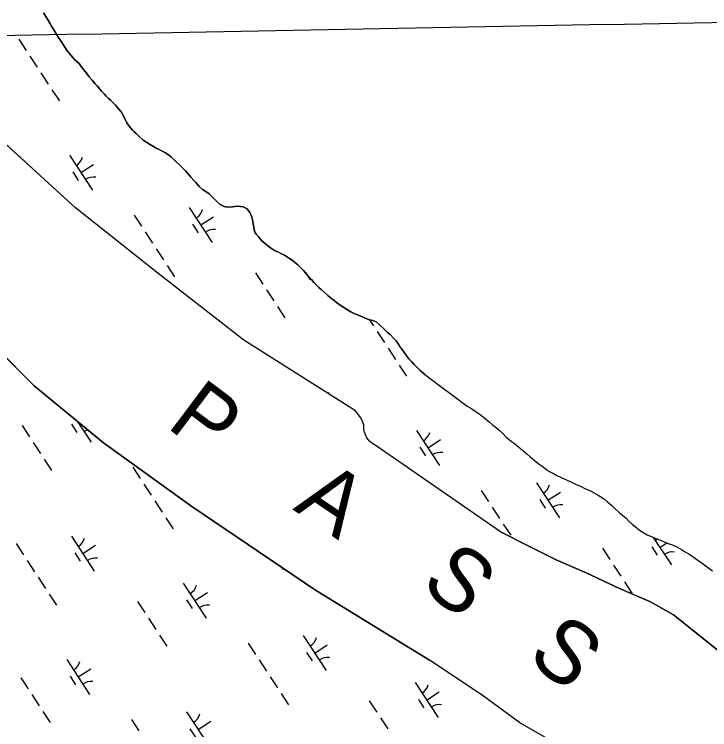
# Model space of a CAD drawing. Extents: x 3945642 to 3966284, y 206476 to 228921.
# Drawn here: x 3957964 to 3958793, y 217580 to 218434 of the extents above; entities that cross this region are included whole.
import ezdxf

# ---------------------------------------------------------------- set-up
doc = ezdxf.new("R2010")
doc.units = 0
for name, color, linetype in [('V-GRID-MAJR', 7, 'Continuous'), ('V-RIVR-IDEN', 7, 'Continuous'), ('V-TOPO-SHOR', 7, 'Continuous'), ('V-WETL-SWMP', 7, 'Continuous')]:
    doc.layers.add(name, color=color, linetype=linetype)

msp = doc.modelspace()

# ---------------------------------------------------------------- linework, layer by layer
at = {"layer": 'V-GRID-MAJR'}
msp.add_spline([(3951300.5, 218285.91), (3951621.83, 218291.8), (3956944.95, 218389.75), (3962268.05, 218488.48), (3962294.36, 218488.97)], degree=3, dxfattribs=at)
at = {"layer": 'V-TOPO-SHOR'}
for points in [[(3958094.57, 218310.93), (3958091.2, 218317.03), (3958086.44, 218322.83), (3958084.33, 218325.19), (3958080.83, 218328.73), (3958078.39, 218330.99), (3958076.06, 218333.25), (3958072.78, 218336.47), (3958070.55, 218338.62), (3958067.59, 218341.95), (3958065.58, 218344.31), (3958062.51, 218348.07), (3958060.08, 218350.75), (3958056.37, 218355.04), (3958052.46, 218359.55), (3958050.13, 218362.88), (3958046.33, 218367.49), (3958043.47, 218371.35), (3958040.83, 218374.78), (3958036.06, 218378.87), (3958033.31, 218381.98), (3958030.77, 218384.67), (3958026.96, 218389.71), (3958024.75, 218393.35), (3958021.05, 218398.71), (3958018.62, 218402.25), (3958015.14, 218407.51), (3958012.93, 218410.93), (3958011.03, 218414.36), (3958008.08, 218419.61), (3958006.08, 218422.93), (3958003.23, 218427.86), (3958001.33, 218430.96), (3957998.48, 218435.57)], [(3958543.75, 217815.94), (3958395.45, 217918.66), (3958390.25, 217921.68), (3958387.38, 217924.05), (3958384.32, 217927.91), (3958382.01, 217932.84), (3958381.06, 217935.62), (3958380.66, 217938.71), (3958380.48, 217942.98), (3958379.44, 217946.62), (3958377.02, 217951.86), (3958370.79, 217960.23), (3958237.29, 218044.6), (3958136.61, 218123.19), (3958036.58, 218202.74), (3957916.91, 218311.66)], [(3958453.5, 218003.59), (3958450.1, 218006.39), (3958447.45, 218008.75), (3958443.75, 218012.4), (3958440.15, 218016.06), (3958437.39, 218018.96), (3958434.43, 218022.29), (3958431.79, 218025.61), (3958428.19, 218030.54), (3958423.65, 218037.19), (3958421.97, 218039.98), (3958419.01, 218043.94), (3958416.47, 218046.52), (3958411.91, 218051.25), (3958408.52, 218054.26), (3958404.7, 218057.7), (3958398.87, 218063.18), (3958395.16, 218066.41), (3958391.33, 218067.93), (3958387.18, 218069.03), (3958384.2, 218070.11), (3958378.89, 218072.39), (3958371.86, 218075.22), (3958368.99, 218076.3), (3958364.95, 218078.36), (3958361.13, 218080.73), (3958355.39, 218084.61), (3958352.42, 218086.45), (3958347.86, 218089.79), (3958344.99, 218092.05), (3958340.54, 218095.6), (3958337.78, 218097.86), (3958333.54, 218101.41), (3958329.62, 218105.07), (3958326.86, 218107.54), (3958323.05, 218111.3), (3958320.93, 218113.66), (3958318.07, 218117.1), (3958313.52, 218122.25), (3958310.56, 218125.58), (3958308.55, 218127.83), (3958304.21, 218132.24), (3958301.77, 218134.39), (3958297.85, 218137.83), (3958295.19, 218139.99), (3958290.73, 218143), (3958285.74, 218145.92), (3958282.45, 218147.65), (3958277.88, 218150.03), (3958274.79, 218151.33), (3958270.65, 218153.6), (3958265.87, 218157.05), (3958261, 218161.46), (3958258.66, 218163.61), (3958255.17, 218167.47), (3958252, 218171.12), (3958250.21, 218174.55), (3958249.49, 218179.46), (3958248.67, 218183.2), (3958247.85, 218188.65), (3958246.18, 218193.67), (3958244.71, 218196.88), (3958241.22, 218201.28), (3958236.55, 218203.66), (3958230.26, 218204.45), (3958223.43, 218203.76), (3958217.77, 218203.48), (3958213.93, 218204.14), (3958208.3, 218206.96), (3958202.9, 218212.44), (3958200.46, 218215.12), (3958195.9, 218219.21), (3958193.15, 218221.25), (3958188.05, 218224.38), (3958184.55, 218227.5), (3958180, 218232.65), (3958177.77, 218235.23), (3958174.18, 218239.1), (3958170.79, 218243.28), (3958168.04, 218246.18), (3958164.02, 218250.48), (3958160.95, 218253.49), (3958156.39, 218258), (3958150.88, 218263.48), (3958146.42, 218266.6), (3958143.77, 218268.22), (3958139.94, 218270.38), (3958137.07, 218271.79), (3958132.71, 218273.96), (3958129.42, 218275.79), (3958124.64, 218278.49), (3958121.56, 218280.44), (3958117.42, 218283.24), (3958112.01, 218288.08), (3958108.83, 218291.2), (3958106.61, 218293.34), (3958104.49, 218295.49), (3958100.47, 218300.22), (3958097.94, 218304.07), (3958095.94, 218308.04), (3958094.57, 218310.93)], [(3957697, 218274.92), (3957707.71, 218265.35), (3957741.57, 218242.07), (3957792.74, 218191.99), (3957847.35, 218130.16), (3957917.47, 218059.68), (3957987.17, 217990.27), (3958070, 217922.04), (3958175.5, 217845.87), (3958322.86, 217746.14), (3958459.02, 217662.71)], [(3958453.5, 218003.59), (3958503.86, 217966.01), (3958509.32, 217962.82), (3958513.55, 217960.06), (3958516.55, 217957.99), (3958521.32, 217954.4), (3958525, 217951.5), (3958530.32, 217947.09), (3958533.86, 217944.05), (3958538.9, 217939.78), (3958541.9, 217937.02), (3958546.26, 217933.02), (3958550.48, 217928.89), (3958553.48, 217926.41), (3958556.75, 217923.79), (3958560.16, 217921.16), (3958565.47, 217916.75), (3958569.43, 217913.71), (3958575.01, 217909.02), (3958578.69, 217905.85), (3958584.42, 217901.16), (3958589.73, 217896.75), (3958593.41, 217894.12), (3958598.73, 217890.12), (3958602.28, 217887.91), (3958607.6, 217884.86), (3958610.74, 217883.2), (3958615.93, 217880.57), (3958619.48, 217879.18), (3958623.31, 217877.51), (3958629.04, 217874.74), (3958633.27, 217872.66), (3958639.83, 217869.75), (3958644.34, 217867.66), (3958650.89, 217864.75), (3958654.72, 217862.67), (3958660.31, 217859.63), (3958663.45, 217857.69), (3958667.81, 217854.65), (3958671.5, 217851.75), (3958676.4, 217847.34), (3958679.8, 217844.04), (3958685.52, 217838.66), (3958689.61, 217835.35), (3958693.43, 217832.04), (3958697.1, 217828.18), (3958701.19, 217824.6), (3958704.73, 217821.7), (3958710.6, 217817.15), (3958714.55, 217814.52), (3958718.65, 217812.31), (3958725.48, 217809.39), (3958730.12, 217807.45), (3958737.5, 217804.53), (3958742.42, 217802.44), (3958749.66, 217799.8), (3958753.89, 217797.72)], [(3958543.75, 217815.94), (3958577.61, 217798.82), (3958609.96, 217782.4), (3958645.93, 217766.86), (3958685.78, 217748.29), (3958722.65, 217732.15), (3958750.2, 217716.66), (3958774.13, 217697.59), (3958803.44, 217674.28)], [(3958753.89, 217797.72), (3958759.63, 217794.67), (3958763.31, 217792.46), (3958768.77, 217789.14), (3958774.36, 217785.41), (3958778.04, 217782.65), (3958782, 217780.02), (3958785.95, 217777.12), (3958792.36, 217772.43), (3958796.73, 217769.25)], [(3959513.7, 217029.24), (3959428.04, 217072.36), (3959348.4, 217116.4), (3959292.43, 217144.73), (3959207.19, 217188.95), (3959155.07, 217220.12), (3959090.4, 217255.2), (3959023.7, 217294.93), (3958962.33, 217334.09), (3958901.76, 217369.41), (3958818.07, 217421.27), (3958770.45, 217452.55), (3958717.55, 217491.38), (3958661.35, 217526.82), (3958607.62, 217564.15), (3958566.65, 217587.89), (3958521.77, 217620.93), (3958459.02, 217662.71)]]:
    msp.add_lwpolyline(points, dxfattribs=at)
at = {"layer": 'V-WETL-SWMP'}
for p, q in [((3957998.48, 218435.57), (3958001.33, 218430.96)), ((3958001.33, 218430.96), (3958003.23, 218427.86)), ((3958003.23, 218427.86), (3958006.08, 218422.93)), ((3958006.08, 218422.93), (3958008.08, 218419.61)), ((3958008.08, 218419.61), (3958011.03, 218414.36)), ((3958011.03, 218414.36), (3958012.93, 218410.93)), ((3958012.93, 218410.93), (3958015.14, 218407.5)), ((3958015.14, 218407.5), (3958018.62, 218402.25)), ((3957969.03, 218403.84), (3957977.8, 218390.45)), ((3958018.62, 218402.25), (3958021.05, 218398.71)), ((3958021.05, 218398.71), (3958024.75, 218393.35)), ((3958024.75, 218393.35), (3958026.96, 218389.71)), ((3958026.96, 218389.71), (3958030.77, 218384.67)), ((3957982.18, 218383.76), (3957990.95, 218370.38)), ((3958030.77, 218384.67), (3958033.31, 218381.98)), ((3958033.31, 218381.98), (3958036.06, 218378.87)), ((3958036.06, 218378.87), (3958040.83, 218374.78)), ((3958040.83, 218374.78), (3958043.47, 218371.35)), ((3958043.47, 218371.35), (3958046.33, 218367.49)), ((3958046.33, 218367.49), (3958050.13, 218362.88)), ((3957995.33, 218363.68), (3958004.1, 218350.3)), ((3958050.13, 218362.88), (3958052.46, 218359.55)), ((3958052.46, 218359.55), (3958056.37, 218355.04)), ((3958056.37, 218355.04), (3958060.08, 218350.75)), ((3958060.08, 218350.75), (3958062.51, 218348.07)), ((3958062.51, 218348.07), (3958065.58, 218344.31)), ((3958008.49, 218343.61), (3958017.25, 218330.23)), ((3958065.58, 218344.31), (3958067.59, 218341.95)), ((3958067.59, 218341.95), (3958070.55, 218338.62)), ((3958070.55, 218338.62), (3958072.78, 218336.47)), ((3958072.78, 218336.47), (3958076.06, 218333.25)), ((3958076.06, 218333.25), (3958078.39, 218330.99)), ((3958078.39, 218330.99), (3958080.83, 218328.73)), ((3958080.83, 218328.73), (3958084.32, 218325.19)), ((3958084.32, 218325.19), (3958086.44, 218322.83)), ((3958086.44, 218322.83), (3958091.2, 218317.03)), ((3958091.2, 218317.03), (3958094.57, 218310.93)), ((3958036.58, 218202.74), (3957916.91, 218311.66)), ((3958094.57, 218310.93), (3958095.94, 218308.04)), ((3958095.94, 218308.04), (3958097.94, 218304.07)), ((3958097.94, 218304.07), (3958100.47, 218300.22)), ((3958100.47, 218300.22), (3958104.49, 218295.49)), ((3958104.49, 218295.49), (3958106.61, 218293.34)), ((3958106.61, 218293.34), (3958108.83, 218291.2)), ((3958108.83, 218291.2), (3958112.01, 218288.08)), ((3958112.01, 218288.08), (3958117.42, 218283.24)), ((3958117.42, 218283.24), (3958121.56, 218280.44)), ((3958121.56, 218280.44), (3958124.64, 218278.49)), ((3958124.64, 218278.49), (3958129.42, 218275.79)), ((3958129.42, 218275.79), (3958132.71, 218273.96)), ((3958132.71, 218273.96), (3958137.07, 218271.79)), ((3958137.07, 218271.79), (3958139.94, 218270.38)), ((3958139.94, 218270.38), (3958143.77, 218268.22)), ((3958029.27, 218265.58), (3958056.67, 218223.76)), ((3958143.77, 218268.22), (3958146.42, 218266.6)), ((3958146.42, 218266.6), (3958150.88, 218263.48)), ((3958150.88, 218263.48), (3958156.39, 218258)), ((3958042.97, 218244.67), (3958058.03, 218254.53)), ((3958156.39, 218258), (3958160.94, 218253.49)), ((3958160.94, 218253.49), (3958164.02, 218250.48)), ((3958033.23, 218245.46), (3958039.8, 218235.42)), ((3958164.02, 218250.48), (3958168.04, 218246.18)), ((3958168.04, 218246.18), (3958170.79, 218243.28)), ((3958170.79, 218243.28), (3958174.18, 218239.1)), ((3958174.18, 218239.1), (3958177.78, 218235.23)), ((3958177.78, 218235.23), (3958180, 218232.65)), ((3958180, 218232.65), (3958184.55, 218227.5)), ((3958184.55, 218227.5), (3958188.05, 218224.38)), ((3958188.05, 218224.38), (3958193.15, 218221.25)), ((3958193.15, 218221.25), (3958195.91, 218219.21)), ((3958195.91, 218219.21), (3958200.46, 218215.12)), ((3958200.46, 218215.12), (3958202.9, 218212.44)), ((3958202.9, 218212.44), (3958208.3, 218206.96)), ((3958136.61, 218123.19), (3958036.58, 218202.74)), ((3958172.34, 218203.04), (3958199.74, 218161.22)), ((3958208.3, 218206.96), (3958213.93, 218204.14)), ((3958213.93, 218204.14), (3958217.77, 218203.48)), ((3958217.77, 218203.48), (3958223.43, 218203.76)), ((3958223.43, 218203.76), (3958230.26, 218204.45)), ((3958230.26, 218204.45), (3958236.55, 218203.66)), ((3958236.55, 218203.66), (3958241.22, 218201.28)), ((3958106.55, 218193.92), (3958115.32, 218180.53)), ((3958241.22, 218201.28), (3958244.71, 218196.88)), ((3958244.71, 218196.88), (3958246.18, 218193.67)), ((3958246.18, 218193.67), (3958247.85, 218188.65)), ((3958186.04, 218182.13), (3958201.1, 218191.99)), ((3958247.85, 218188.65), (3958248.67, 218183.2)), ((3958176.3, 218182.92), (3958182.88, 218172.88)), ((3958248.67, 218183.2), (3958249.5, 218179.46)), ((3958249.5, 218179.46), (3958250.21, 218174.55)), ((3958119.7, 218173.84), (3958128.47, 218160.46)), ((3958250.21, 218174.55), (3958252, 218171.12)), ((3958252, 218171.12), (3958255.17, 218167.47)), ((3958255.17, 218167.47), (3958258.66, 218163.61)), ((3958258.66, 218163.61), (3958261, 218161.46)), ((3958261, 218161.46), (3958265.87, 218157.05)), ((3958132.85, 218153.77), (3958141.62, 218140.38)), ((3958265.87, 218157.05), (3958270.65, 218153.6)), ((3958270.65, 218153.6), (3958274.79, 218151.33)), ((3958274.79, 218151.33), (3958277.88, 218150.03)), ((3958277.88, 218150.03), (3958282.45, 218147.65)), ((3958282.45, 218147.65), (3958285.74, 218145.92)), ((3958285.74, 218145.92), (3958290.73, 218143)), ((3958290.73, 218143), (3958295.19, 218139.98)), ((3958146.01, 218133.69), (3958154.77, 218120.31)), ((3958295.19, 218139.98), (3958297.85, 218137.83)), ((3958297.85, 218137.83), (3958301.77, 218134.39)), ((3958301.77, 218134.39), (3958304.21, 218132.24)), ((3958251.24, 218124.98), (3958260.01, 218111.59)), ((3958304.21, 218132.24), (3958308.55, 218127.83)), ((3958308.55, 218127.83), (3958310.56, 218125.58)), ((3958310.56, 218125.58), (3958313.52, 218122.25)), ((3958310.78, 218125.33), (3958316.46, 218116.66)), ((3958237.29, 218044.6), (3958136.61, 218123.19)), ((3958313.52, 218122.25), (3958318.07, 218117.1)), ((3958318.07, 218117.1), (3958320.93, 218113.66)), ((3958320.93, 218113.66), (3958323.05, 218111.3)), ((3958323.05, 218111.3), (3958326.86, 218107.54)), ((3958264.39, 218104.9), (3958273.16, 218091.52)), ((3958326.86, 218107.54), (3958329.62, 218105.07)), ((3958329.62, 218105.07), (3958333.54, 218101.41)), ((3958333.54, 218101.41), (3958337.78, 218097.86)), ((3958337.78, 218097.86), (3958340.54, 218095.6)), ((3958340.54, 218095.6), (3958344.99, 218092.05)), ((3958344.99, 218092.05), (3958347.86, 218089.79)), ((3958277.54, 218084.83), (3958286.31, 218071.44)), ((3958347.86, 218089.79), (3958352.42, 218086.45)), ((3958352.42, 218086.45), (3958355.39, 218084.61)), ((3958355.39, 218084.61), (3958361.13, 218080.73)), ((3958361.13, 218080.73), (3958364.95, 218078.36)), ((3958364.95, 218078.36), (3958368.99, 218076.3)), ((3958368.99, 218076.3), (3958371.86, 218075.22)), ((3958371.86, 218075.22), (3958378.88, 218072.39)), ((3958378.88, 218072.39), (3958384.2, 218070.11)), ((3958384.2, 218070.11), (3958387.18, 218069.03)), ((3958387.18, 218069.03), (3958391.33, 218067.93)), ((3958387.23, 218069.01), (3958391.98, 218061.77)), ((3958391.33, 218067.93), (3958395.16, 218066.41)), ((3958395.16, 218066.41), (3958398.87, 218063.18)), ((3957987.17, 217990.27), (3957917.47, 218059.68)), ((3958398.87, 218063.18), (3958404.7, 218057.7)), ((3958404.7, 218057.7), (3958408.52, 218054.26)), ((3958396.36, 218055.07), (3958405.13, 218041.69)), ((3958408.52, 218054.26), (3958411.91, 218051.25)), ((3958411.91, 218051.25), (3958416.46, 218046.52)), ((3958370.79, 217960.23), (3958237.29, 218044.6)), ((3958416.46, 218046.52), (3958419.01, 218043.94)), ((3958419.01, 218043.94), (3958421.97, 218039.98)), ((3958421.97, 218039.98), (3958423.65, 218037.19)), ((3958409.51, 218035), (3958418.28, 218021.61)), ((3958423.65, 218037.19), (3958428.19, 218030.54)), ((3958428.19, 218030.54), (3958431.79, 218025.61)), ((3958431.79, 218025.61), (3958434.43, 218022.29)), ((3958422.66, 218014.92), (3958431.43, 218001.54)), ((3958434.43, 218022.29), (3958437.39, 218018.96)), ((3958437.39, 218018.96), (3958440.14, 218016.06)), ((3958440.14, 218016.06), (3958443.75, 218012.4)), ((3958443.75, 218012.4), (3958447.45, 218008.75)), ((3958447.45, 218008.75), (3958450.1, 218006.39)), ((3958450.1, 218006.39), (3958453.5, 218003.59)), ((3958453.5, 218003.59), (3958503.86, 217966.01)), ((3958070, 217922.04), (3957987.17, 217990.27)), ((3958337.44, 217981.3), (3958338.62, 217982.07)), ((3958503.86, 217966.01), (3958509.32, 217962.82)), ((3958509.32, 217962.82), (3958513.55, 217960.06)), ((3958377.02, 217951.86), (3958370.79, 217960.23)), ((3958513.55, 217960.06), (3958516.55, 217957.99)), ((3958516.55, 217957.99), (3958521.32, 217954.4)), ((3958521.32, 217954.4), (3958525, 217951.5)), ((3958038.45, 217948.02), (3958055.05, 217922.69)), ((3958379.44, 217946.62), (3958377.02, 217951.86)), ((3958380.48, 217942.98), (3958379.44, 217946.62)), ((3958525, 217951.5), (3958530.32, 217947.09)), ((3958530.32, 217947.09), (3958533.86, 217944.05)), ((3957972.96, 217942.67), (3957981.73, 217929.29)), ((3958031.61, 217944.39), (3958038.19, 217934.35)), ((3958041.35, 217943.6), (3958042.73, 217944.5)), ((3958380.66, 217938.71), (3958380.48, 217942.98)), ((3958381.06, 217935.62), (3958380.66, 217938.71)), ((3958533.86, 217944.05), (3958538.9, 217939.78)), ((3958538.9, 217939.78), (3958541.9, 217937.02)), ((3958382, 217932.84), (3958381.06, 217935.62)), ((3958384.32, 217927.92), (3958382, 217932.84)), ((3958443.45, 217936.9), (3958470.85, 217895.07)), ((3958541.9, 217937.02), (3958546.26, 217933.02)), ((3958546.26, 217933.02), (3958550.48, 217928.89)), ((3958550.48, 217928.89), (3958553.48, 217926.41)), ((3957986.11, 217922.6), (3957994.88, 217909.22)), ((3958175.5, 217845.87), (3958070, 217922.04)), ((3958387.38, 217924.05), (3958384.32, 217927.92)), ((3958390.25, 217921.68), (3958387.38, 217924.05)), ((3958395.45, 217918.66), (3958390.25, 217921.68)), ((3958457.15, 217915.98), (3958472.21, 217925.85)), ((3958553.48, 217926.41), (3958556.75, 217923.79)), ((3958556.75, 217923.79), (3958560.16, 217921.16)), ((3958560.16, 217921.16), (3958565.47, 217916.75)), ((3958543.75, 217815.94), (3958395.45, 217918.66)), ((3958447.41, 217916.77), (3958453.98, 217906.74)), ((3958565.47, 217916.75), (3958569.43, 217913.71)), ((3958569.43, 217913.71), (3958575.01, 217909.02)), ((3958575.01, 217909.02), (3958578.69, 217905.85)), ((3958578.69, 217905.85), (3958584.42, 217901.16)), ((3957999.26, 217902.52), (3958008.03, 217889.14)), ((3958584.42, 217901.16), (3958589.73, 217896.75)), ((3958589.73, 217896.75), (3958593.41, 217894.12)), ((3958104.93, 217892.85), (3958113.7, 217879.46)), ((3958593.41, 217894.12), (3958598.73, 217890.12)), ((3958598.73, 217890.12), (3958602.28, 217887.91)), ((3958602.28, 217887.91), (3958607.6, 217884.86)), ((3958607.6, 217884.86), (3958610.74, 217883.2)), ((3958610.74, 217883.2), (3958615.93, 217880.57)), ((3958615.93, 217880.57), (3958619.48, 217879.18)), ((3958619.48, 217879.18), (3958623.31, 217877.51)), ((3958623.31, 217877.51), (3958629.04, 217874.74)), ((3958118.08, 217872.77), (3958126.85, 217859.39)), ((3958586.52, 217874.35), (3958613.92, 217832.53)), ((3958629.04, 217874.74), (3958633.27, 217872.66)), ((3958633.27, 217872.66), (3958639.83, 217869.75)), ((3958639.83, 217869.75), (3958644.34, 217867.66)), ((3958520.73, 217865.23), (3958529.5, 217851.85)), ((3958600.22, 217853.44), (3958615.28, 217863.31)), ((3958644.34, 217867.66), (3958650.89, 217864.75)), ((3958650.89, 217864.75), (3958654.72, 217862.67)), ((3958654.72, 217862.67), (3958660.31, 217859.63)), ((3958131.24, 217852.7), (3958140, 217839.31)), ((3958590.48, 217854.23), (3958597.06, 217844.2)), ((3958660.31, 217859.63), (3958663.45, 217857.69)), ((3958663.45, 217857.69), (3958667.81, 217854.65)), ((3958667.81, 217854.65), (3958671.5, 217851.75)), ((3958671.5, 217851.75), (3958676.4, 217847.34)), ((3958322.86, 217746.14), (3958175.5, 217845.87)), ((3958533.88, 217845.15), (3958542.65, 217831.77)), ((3958676.4, 217847.34), (3958679.8, 217844.04)), ((3958679.8, 217844.04), (3958685.52, 217838.66)), ((3958685.52, 217838.66), (3958689.61, 217835.35)), ((3958689.61, 217835.35), (3958693.43, 217832.04)), ((3958144.39, 217832.62), (3958153.16, 217819.24)), ((3958693.43, 217832.04), (3958697.1, 217828.18)), ((3958697.1, 217828.18), (3958701.19, 217824.6)), ((3958547.03, 217825.08), (3958555.8, 217811.7)), ((3958701.19, 217824.6), (3958704.73, 217821.7)), ((3958704.73, 217821.7), (3958710.6, 217817.15)), ((3958031.59, 217810.82), (3958058.99, 217769)), ((3958577.61, 217798.82), (3958543.75, 217815.94)), ((3958710.6, 217817.15), (3958714.55, 217814.52)), ((3958714.55, 217814.52), (3958718.65, 217812.31)), ((3958718.65, 217812.31), (3958725.48, 217809.39)), ((3958725.48, 217809.39), (3958730.12, 217807.45)), ((3958725.97, 217809.19), (3958747.51, 217776.3)), ((3957965.79, 217801.7), (3957974.56, 217788.31)), ((3958730.12, 217807.45), (3958737.5, 217804.53)), ((3958733.81, 217797.22), (3958742.03, 217802.6)), ((3958737.5, 217804.53), (3958742.42, 217802.44)), ((3958742.42, 217802.44), (3958749.66, 217799.8)), ((3958045.29, 217789.91), (3958060.34, 217799.77)), ((3958609.96, 217782.4), (3958577.61, 217798.82)), ((3958665.42, 217796.29), (3958674.19, 217782.91)), ((3958724.07, 217798.01), (3958730.64, 217787.97)), ((3958749.66, 217799.8), (3958753.89, 217797.72)), ((3958753.89, 217797.72), (3958759.63, 217794.67)), ((3958759.63, 217794.67), (3958763.31, 217792.46)), ((3958763.31, 217792.46), (3958768.77, 217789.14)), ((3958035.55, 217790.7), (3958042.12, 217780.66)), ((3958768.77, 217789.14), (3958774.36, 217785.41)), ((3958774.36, 217785.41), (3958778.04, 217782.65)), ((3957978.95, 217781.62), (3957987.71, 217768.24)), ((3958645.93, 217766.86), (3958609.96, 217782.4)), ((3958678.57, 217776.22), (3958687.34, 217762.83)), ((3958778.04, 217782.65), (3958782, 217780.02)), ((3958782, 217780.02), (3958785.95, 217777.12)), ((3958785.95, 217777.12), (3958792.36, 217772.43)), ((3958282.81, 217773.25), (3958284.69, 217770.37)), ((3958685.78, 217748.29), (3958645.93, 217766.86)), ((3958792.36, 217772.43), (3958796.73, 217769.25)), ((3957992.1, 217761.54), (3958000.86, 217748.16)), ((3958165.17, 217754.59), (3958192.57, 217712.77)), ((3958691.72, 217756.14), (3958700.49, 217742.76)), ((3958005.25, 217741.47), (3958014.02, 217728.08)), ((3958178.87, 217733.68), (3958193.93, 217743.54)), ((3958459.02, 217662.71), (3958322.86, 217746.14)), ((3958722.65, 217732.15), (3958685.78, 217748.29)), ((3958110.48, 217732.76), (3958119.25, 217719.37)), ((3958169.13, 217734.47), (3958175.71, 217724.43)), ((3958750.2, 217716.66), (3958722.65, 217732.15)), ((3958774.13, 217697.59), (3958750.2, 217716.66)), ((3958123.63, 217712.68), (3958132.4, 217699.3)), ((3958136.78, 217692.6), (3958145.55, 217679.22)), ((3958308.25, 217692.05), (3958335.65, 217650.23)), ((3958803.44, 217674.28), (3958774.13, 217697.59)), ((3958242.45, 217682.93), (3958251.22, 217669.54)), ((3958321.95, 217671.14), (3958337, 217681)), ((3958312.2, 217671.93), (3958318.78, 217661.89)), ((3958026.03, 217663.44), (3958053.43, 217621.62)), ((3958255.6, 217662.85), (3958264.37, 217649.47)), ((3958521.77, 217620.93), (3958459.02, 217662.71)), ((3958039.73, 217642.53), (3958054.79, 217652.39)), ((3957971.34, 217641.6), (3957980.11, 217628.22)), ((3958029.99, 217643.32), (3958036.57, 217633.28)), ((3958268.76, 217642.78), (3958277.52, 217629.39)), ((3958441.83, 217635.83), (3958469.23, 217594)), ((3957984.49, 217621.53), (3957993.26, 217608.14)), ((3958281.91, 217622.7), (3958290.68, 217609.32)), ((3958455.53, 217614.91), (3958470.59, 217624.78)), ((3958387.14, 217613.99), (3958395.91, 217600.6)), ((3958445.79, 217615.7), (3958452.37, 217605.67)), ((3958566.65, 217587.89), (3958521.77, 217620.93)), ((3957997.65, 217601.45), (3958006.41, 217588.07)), ((3958169.11, 217600.9), (3958196.51, 217559.08)), ((3958103.31, 217591.78), (3958112.08, 217578.39)), ((3958182.81, 217579.99), (3958197.86, 217589.85)), ((3958400.29, 217593.91), (3958409.06, 217580.53)), ((3958607.62, 217564.15), (3958566.65, 217587.89)), ((3958173.07, 217580.78), (3958179.64, 217570.74))]:
    msp.add_line(p, q, dxfattribs=at)
for centre, start, end in [((3958028.03, 218267.91), 302.45745, 344.00111), ((3958058.31, 218221.7), 82.45745, 124.00111), ((3958171.11, 218205.36), 302.45745, 344.00111), ((3958201.38, 218159.15), 82.45745, 124.00111), ((3958308.63, 217995.45), 338.96074, 344.00111), ((3958056.69, 217920.63), 107.68421, 124.00111), ((3958442.21, 217939.22), 302.45745, 344.00111), ((3958472.48, 217893.01), 82.45745, 124.00111), ((3958585.29, 217876.68), 302.45745, 344.00111), ((3958615.56, 217830.47), 82.45745, 124.00111), ((3958030.35, 217813.14), 302.45745, 344.00111), ((3958718.87, 217820.45), 302.45745, 311.58256), ((3958749.14, 217774.24), 82.45745, 124.00111), ((3958060.62, 217766.93), 82.45745, 124.00111), ((3958163.93, 217756.92), 302.45745, 344.00111), ((3958194.21, 217710.71), 82.45745, 124.00111), ((3958307.01, 217694.37), 302.45745, 344.00111), ((3958337.28, 217648.16), 82.45745, 124.00111), ((3958024.8, 217665.76), 302.45745, 344.00111), ((3958055.07, 217619.55), 82.45745, 124.00111), ((3958440.59, 217638.15), 302.45745, 344.00111), ((3958470.87, 217591.94), 82.45745, 124.00111), ((3958167.87, 217603.22), 302.45745, 344.00111)]:
    msp.add_arc(centre, 17.62, start, end, dxfattribs=at)

# ---------------------------------------------------------------- texts
at = {"layer": 'V-RIVR-IDEN'}
for s, rotation, p in [('P', 323.08417, (3958143.62, 217941.5)), ('A', 326.08417, (3958295.05, 217842.76)), ('S', 321.08417, (3958446.28, 217750.87)), ('S', 321.08417, (3958573.42, 217664.61))]:
    msp.add_text(s, height=75, rotation=rotation, dxfattribs=at).set_placement(p)

doc.saveas('drawing.dxf')
